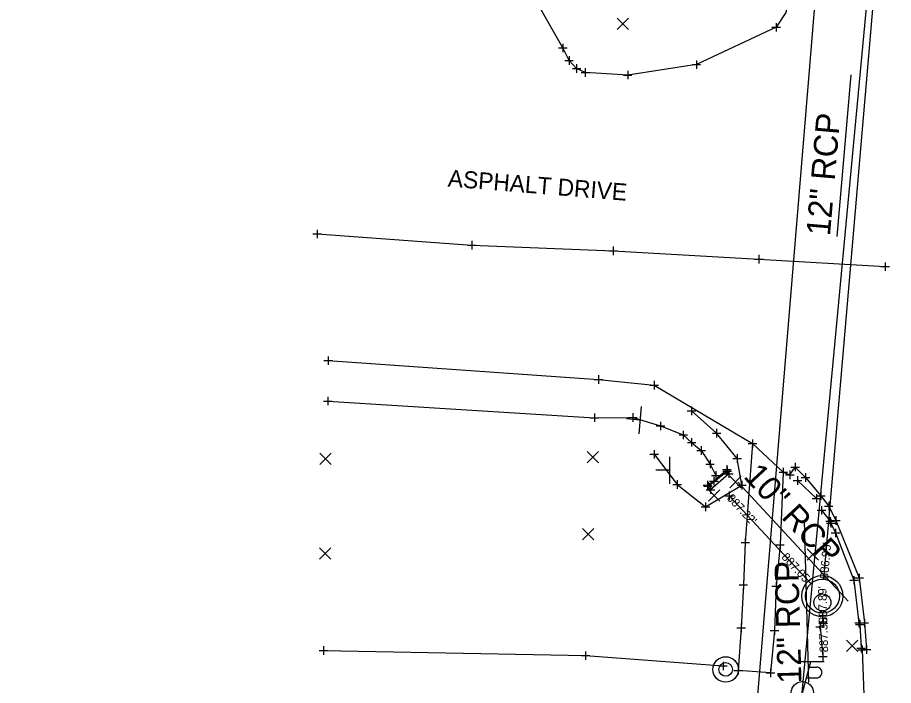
# Model space of a CAD drawing. Extents: x 1380440 to 1381945, y 468756 to 470369.
# Drawn here: x 1381467.5 to 1381570.5, y 469758.2 to 469836.8 of the extents above; entities that cross this region are included whole.
import ezdxf

# ---------------------------------------------------------------- set-up
doc = ezdxf.new("R2010")
doc.units = 0
for name, color, linetype in [('DR_P_Headwall', 7, 'Continuous'), ('DR_X_Cells', 7, 'Continuous'), ('DV_X_Lot_Line', 7, 'Continuous'), ('GE_P_Driveway_CL', 7, 'Continuous'), ('GK_Drainage_Nodes', 7, 'Continuous'), ('PV_P_Curb', 7, 'Continuous'), ('PV_P_Curb_Ramp', 7, 'Continuous'), ('PV_P_Drive', 7, 'Continuous'), ('PV_P_Joint', 7, 'Continuous'), ('PV_P_Parking_Lot', 7, 'Continuous'), ('PV_P_Saw_Cut_Line', 7, 'Continuous'), ('PV_X_COP', 7, 'Continuous'), ('RW_P_Esmt_TMP', 7, 'Continuous'), ('RW_X_CL', 7, 'Continuous'), ('SC_Scratch1', 7, 'Continuous'), ('SC_Scratch3', 7, 'Continuous'), ('SC_Shading1', 7, 'Continuous'), ('SH_Named_Boundary', 7, 'Continuous'), ('UT_X_Gas', 7, 'Continuous'), ('UT_X_Overhead_Combined', 7, 'Continuous'), ('X-CL', 7, 'Continuous'), ('X-SUBDIVISION', 7, 'Continuous')]:
    doc.layers.add(name, color=color, linetype=linetype)

msp = doc.modelspace()

# ---------------------------------------------------------------- linework, layer by layer
at = {"layer": 'DR_P_Headwall'}
for points in [[(1381553.91, 469786.69), (1381553.07, 469775.06), (1381552.84, 469770.08), (1381552.59, 469765.03), (1381552.22, 469760.02)], [(1381557.54, 469783.33), (1381557.15, 469774.79), (1381556.68, 469769.93), (1381556.5, 469764.72), (1381556.04, 469759.73), (1381552.22, 469760.02)]]:
    msp.add_lwpolyline(points, dxfattribs=at)
at = {"layer": 'DR_X_Cells'}
for points in [[(1381559.2, 469782.35), (1381561.45, 469780.25)], [(1381562.03, 469778.85), (1381563.05, 469777.56)], [(1381563.12, 469777.33), (1381563.68, 469776.18), (1381565.84, 469770.62), (1381566.43, 469765.62)], [(1381566.53, 469765.42), (1381566.69, 469762.64)]]:
    msp.add_lwpolyline(points, dxfattribs=at)
at = {"layer": 'DV_X_Lot_Line'}
msp.add_lwpolyline([(1381550.89, 469783.64), (1381549.38, 469782.29), (1381548.61, 469781.82)], dxfattribs=at)
at = {"layer": 'GE_P_Driveway_CL'}
for p, q in [((1381538.02, 469835.38), (1381539.35, 469836.71)), ((1381538.02, 469836.71), (1381539.35, 469835.38)), ((1381534.48, 469784.45), (1381535.82, 469785.78)), ((1381534.48, 469785.78), (1381535.82, 469784.45)), ((1381503.05, 469784.24), (1381504.38, 469785.58)), ((1381503.05, 469785.58), (1381504.38, 469784.24)), ((1381551.24, 469781.51), (1381552.57, 469782.85)), ((1381551.24, 469782.85), (1381552.57, 469781.51)), ((1381548.74, 469779.94), (1381550.07, 469781.27)), ((1381548.74, 469781.27), (1381550.07, 469779.94)), ((1381533.92, 469775.39), (1381535.26, 469776.72)), ((1381533.92, 469776.72), (1381535.26, 469775.39)), ((1381503, 469773.09), (1381504.33, 469774.42)), ((1381503, 469774.42), (1381504.33, 469773.09)), ((1381560.35, 469772.98), (1381561.69, 469774.31)), ((1381560.35, 469774.31), (1381561.69, 469772.98)), ((1381564.98, 469762.23), (1381566.31, 469763.57)), ((1381564.98, 469763.57), (1381566.31, 469762.23))]:
    msp.add_line(p, q, dxfattribs=at)
at = {"layer": 'GK_Drainage_Nodes'}
msp.add_lwpolyline([(1381503.48, 469762.36), (1381534.28, 469761.76), (1381550.45, 469760.54)], dxfattribs=at)
at = {"layer": 'PV_P_Curb'}
for points in [[(1381503.97, 469791.7), (1381535.33, 469789.74), (1381539.85, 469789.76), (1381543.1, 469788.77), (1381545.78, 469787.71), (1381546.76, 469786.84), (1381547.89, 469785.89), (1381548.92, 469784.29), (1381549.59, 469782.95)], [(1381561.88, 469765.13), (1381562.19, 469761.65)]]:
    msp.add_lwpolyline(points, dxfattribs=at)
at = {"layer": 'PV_P_Curb_Ramp'}
for p, q in [((1381562.13, 469770.76), (1381562.13, 469770.76)), ((1381562.13, 469768.76), (1381562.13, 469768.76)), ((1381562.13, 469768.76), (1381562.13, 469768.76)), ((1381562.13, 469768.01), (1381562.13, 469768.01)), ((1381562.13, 469766.76), (1381562.13, 469766.76))]:
    msp.add_line(p, q, dxfattribs=at)
msp.add_circle((1381562.13, 469768.76), 2, dxfattribs=at)
at = {"layer": 'PV_P_Drive'}
for p, q in [((1381540.84, 469791.05), (1381540.56, 469787.86)), ((1381540.7, 469789.46), (1381539.11, 469789.6)), ((1381544.16, 469785.15), (1381544.16, 469781.95)), ((1381544.16, 469783.55), (1381542.56, 469783.55))]:
    msp.add_line(p, q, dxfattribs=at)
at = {"layer": 'PV_P_Joint'}
for centre, radius in [((1381562.13, 469768.76), 2.42), ((1381562.13, 469768.76), 2), ((1381562.13, 469768.01), 1)]:
    msp.add_circle(centre, radius, dxfattribs=at)
at = {"layer": 'PV_P_Parking_Lot'}
msp.add_lwpolyline([(1381542.35, 469785.44), (1381545.05, 469781.89), (1381548.39, 469779.26), (1381552.66, 469781.8), (1381552.11, 469784.95), (1381549.7, 469787.92), (1381546.74, 469790.54)], dxfattribs=at)
at = {"layer": 'PV_P_Saw_Cut_Line'}
for p, q in [((1381551.19, 469781.06), (1381551.19, 469780.06)), ((1381550.69, 469780.56), (1381551.69, 469780.56)), ((1381551.19, 469780.56), (1381551.19, 469780.56)), ((1381561.72, 469765.59), (1381562.72, 469765.59)), ((1381562.22, 469766.09), (1381562.22, 469765.09)), ((1381562.22, 469765.59), (1381562.22, 469765.59))]:
    msp.add_line(p, q, dxfattribs=at)
at = {"layer": 'PV_X_COP'}
for p, q in [((1381560.74, 469761.01), (1381559.13, 469755.01)), ((1381562.34, 469761.01), (1381559.14, 469761.01)), ((1381560.58, 469760.41), (1381561.43, 469760.41)), ((1381560.24, 469759.13), (1381561.43, 469759.13))]:
    msp.add_line(p, q, dxfattribs=at)
msp.add_circle((1381559.77, 469757.41), 1.3, dxfattribs=at)
msp.add_arc((1381561.44, 469759.77), 0.638, 268.8767, 91.1233, dxfattribs=at)
at = {"layer": 'RW_P_Esmt_TMP'}
for points in [[(1381558.35, 469840.14), (1381557.85, 469837.4), (1381556.7, 469835.65), (1381547.32, 469831.26), (1381539.24, 469830.04), (1381534.26, 469830.33), (1381533.24, 469830.81), (1381532.35, 469831.75), (1381531.61, 469833.22), (1381528.74, 469838.25), (1381528.06, 469839.33), (1381527.53, 469840.55), (1381527.51, 469841.81), (1381527.73, 469842.93), (1381527.99, 469844.34), (1381528.64, 469852.75), (1381545.21, 469852.93)], [(1381504.03, 469796.45), (1381535.81, 469794.23), (1381542.35, 469793.56), (1381553.91, 469786.69), (1381557.54, 469783.33), (1381558.31, 469783.03), (1381558.93, 469783.94), (1381560.15, 469782.7), (1381561.95, 469780.57), (1381562.88, 469779.33), (1381563.72, 469777.65), (1381566.46, 469770.89), (1381567.07, 469765.6), (1381567.32, 469762.48), (1381566.8, 469762.44), (1381567.31, 469748.74), (1381566.9, 469746.97), (1381566.29, 469730.74), (1381565.48, 469712.75), (1381565.27, 469710.06), (1381564.07, 469691.21), (1381563.72, 469691.13), (1381563.05, 469684.22)]]:
    msp.add_lwpolyline(points, dxfattribs=at)
at = {"layer": 'RW_X_CL'}
for p, q in [((1381565.48, 469830.07), (1381563.85, 469811.05)), ((1381565.16, 469768.17), (1381552.19, 469782.16)), ((1381559.99, 469777.66), (1381560.5, 469758.58))]:
    msp.add_line(p, q, dxfattribs=at)
at = {"layer": 'SC_Scratch1'}
for radius in [1.5, 0.8]:
    msp.add_circle((1381550.76, 469760.13), radius, dxfattribs=at)
at = {"layer": 'SC_Scratch3'}
msp.add_lwpolyline([(1381548.97, 469781.27), (1381548.69, 469781.67), (1381550.93, 469783.46), (1381551.13, 469783.15)], close=True, dxfattribs=at)
at = {"layer": 'SC_Shading1'}
msp.add_lwpolyline([(1381502.74, 469811.35), (1381520.93, 469810.03), (1381537.52, 469809.37), (1381554.67, 469808.38), (1381569.52, 469807.51)], dxfattribs=at)
at = {"layer": 'SH_Named_Boundary'}
for p, q in [((1381556.2, 469835.65), (1381557.2, 469835.65)), ((1381556.7, 469836.15), (1381556.7, 469835.15)), ((1381556.7, 469835.65), (1381556.7, 469835.65)), ((1381531.11, 469833.22), (1381532.11, 469833.22)), ((1381531.61, 469833.72), (1381531.61, 469832.72)), ((1381531.61, 469833.22), (1381531.61, 469833.22)), ((1381532.35, 469832.25), (1381532.35, 469831.25)), ((1381531.85, 469831.75), (1381532.85, 469831.75)), ((1381532.35, 469831.75), (1381532.35, 469831.75)), ((1381533.24, 469831.31), (1381533.24, 469830.31)), ((1381546.82, 469831.26), (1381547.82, 469831.26)), ((1381546.82, 469831.26), (1381547.82, 469831.26)), ((1381547.32, 469831.76), (1381547.32, 469830.76)), ((1381547.32, 469831.76), (1381547.32, 469830.76)), ((1381547.32, 469831.26), (1381547.32, 469831.26)), ((1381547.32, 469831.26), (1381547.32, 469831.26)), ((1381532.74, 469830.81), (1381533.74, 469830.81)), ((1381533.24, 469830.81), (1381533.24, 469830.81)), ((1381533.76, 469830.33), (1381534.76, 469830.33)), ((1381533.76, 469830.33), (1381534.76, 469830.33)), ((1381534.26, 469830.83), (1381534.26, 469829.83)), ((1381534.26, 469830.83), (1381534.26, 469829.83)), ((1381534.26, 469830.33), (1381534.26, 469830.33)), ((1381534.26, 469830.33), (1381534.26, 469830.33)), ((1381539.24, 469830.54), (1381539.24, 469829.54)), ((1381538.74, 469830.04), (1381539.74, 469830.04)), ((1381539.24, 469830.04), (1381539.24, 469830.04)), ((1381502.74, 469811.85), (1381502.74, 469810.85)), ((1381502.24, 469811.35), (1381503.24, 469811.35)), ((1381502.74, 469811.35), (1381502.74, 469811.35)), ((1381520.93, 469810.53), (1381520.93, 469809.53)), ((1381520.43, 469810.03), (1381521.43, 469810.03)), ((1381520.93, 469810.03), (1381520.93, 469810.03)), ((1381537.52, 469809.87), (1381537.52, 469808.87)), ((1381537.02, 469809.37), (1381538.02, 469809.37)), ((1381537.52, 469809.37), (1381537.52, 469809.37)), ((1381554.67, 469808.88), (1381554.67, 469807.88)), ((1381554.17, 469808.38), (1381555.17, 469808.38)), ((1381554.67, 469808.38), (1381554.67, 469808.38)), ((1381569.02, 469807.51), (1381570.02, 469807.51)), ((1381569.52, 469808.01), (1381569.52, 469807.01)), ((1381569.52, 469807.51), (1381569.52, 469807.51)), ((1381503.53, 469796.45), (1381504.53, 469796.45)), ((1381504.03, 469796.95), (1381504.03, 469795.95)), ((1381504.03, 469796.45), (1381504.03, 469796.45)), ((1381535.31, 469794.23), (1381536.31, 469794.23)), ((1381535.81, 469794.73), (1381535.81, 469793.73)), ((1381535.81, 469794.23), (1381535.81, 469794.23)), ((1381542.35, 469794.06), (1381542.35, 469793.06)), ((1381541.85, 469793.56), (1381542.85, 469793.56)), ((1381542.35, 469793.56), (1381542.35, 469793.56)), ((1381503.97, 469792.2), (1381503.97, 469791.2)), ((1381503.47, 469791.7), (1381504.47, 469791.7)), ((1381503.97, 469791.7), (1381503.97, 469791.7)), ((1381546.74, 469791.04), (1381546.74, 469790.04)), ((1381535.33, 469790.24), (1381535.33, 469789.24)), ((1381539.85, 469790.26), (1381539.85, 469789.26)), ((1381546.24, 469790.54), (1381547.24, 469790.54)), ((1381546.74, 469790.54), (1381546.74, 469790.54)), ((1381534.83, 469789.74), (1381535.83, 469789.74)), ((1381535.33, 469789.74), (1381535.33, 469789.74)), ((1381539.35, 469789.76), (1381540.35, 469789.76)), ((1381539.85, 469789.76), (1381539.85, 469789.76)), ((1381543.1, 469789.27), (1381543.1, 469788.27)), ((1381542.6, 469788.77), (1381543.6, 469788.77)), ((1381543.1, 469788.77), (1381543.1, 469788.77)), ((1381545.78, 469788.21), (1381545.78, 469787.21)), ((1381549.2, 469787.92), (1381550.2, 469787.92)), ((1381549.7, 469788.42), (1381549.7, 469787.42)), ((1381549.7, 469787.92), (1381549.7, 469787.92)), ((1381545.28, 469787.71), (1381546.28, 469787.71)), ((1381545.78, 469787.71), (1381545.78, 469787.71)), ((1381546.26, 469786.84), (1381547.26, 469786.84)), ((1381546.76, 469787.34), (1381546.76, 469786.34)), ((1381546.76, 469786.84), (1381546.76, 469786.84)), ((1381553.91, 469787.19), (1381553.91, 469786.19)), ((1381553.91, 469787.19), (1381553.91, 469786.19)), ((1381542.35, 469785.94), (1381542.35, 469784.94)), ((1381547.39, 469785.89), (1381548.39, 469785.89)), ((1381547.89, 469786.39), (1381547.89, 469785.39)), ((1381547.89, 469785.89), (1381547.89, 469785.89)), ((1381553.41, 469786.69), (1381554.41, 469786.69)), ((1381553.41, 469786.69), (1381554.41, 469786.69)), ((1381553.91, 469786.69), (1381553.91, 469786.69)), ((1381553.91, 469786.69), (1381553.91, 469786.69)), ((1381541.85, 469785.44), (1381542.85, 469785.44)), ((1381542.35, 469785.44), (1381542.35, 469785.44)), ((1381548.92, 469784.79), (1381548.92, 469783.79)), ((1381551.61, 469784.95), (1381552.61, 469784.95)), ((1381552.11, 469785.45), (1381552.11, 469784.45)), ((1381552.11, 469784.95), (1381552.11, 469784.95)), ((1381548.42, 469784.29), (1381549.42, 469784.29)), ((1381548.92, 469784.29), (1381548.92, 469784.29)), ((1381550.89, 469784.14), (1381550.89, 469783.14)), ((1381550.93, 469783.96), (1381550.93, 469782.96)), ((1381557.54, 469783.83), (1381557.54, 469782.83)), ((1381557.54, 469783.83), (1381557.54, 469782.83)), ((1381558.43, 469783.94), (1381559.43, 469783.94)), ((1381558.93, 469784.44), (1381558.93, 469783.44)), ((1381558.93, 469783.94), (1381558.93, 469783.94)), ((1381549.09, 469782.95), (1381550.09, 469782.95)), ((1381549.38, 469782.79), (1381549.38, 469781.79)), ((1381549.59, 469783.45), (1381549.59, 469782.45)), ((1381549.59, 469782.95), (1381549.59, 469782.95)), ((1381550.39, 469783.64), (1381551.39, 469783.64)), ((1381550.43, 469783.46), (1381551.43, 469783.46)), ((1381550.63, 469783.15), (1381551.63, 469783.15)), ((1381550.89, 469783.64), (1381550.89, 469783.64)), ((1381550.93, 469783.46), (1381550.93, 469783.46)), ((1381551.13, 469783.65), (1381551.13, 469782.65)), ((1381551.13, 469783.15), (1381551.13, 469783.15)), ((1381557.04, 469783.33), (1381558.04, 469783.33)), ((1381557.04, 469783.33), (1381558.04, 469783.33)), ((1381557.54, 469783.33), (1381557.54, 469783.33)), ((1381557.54, 469783.33), (1381557.54, 469783.33)), ((1381557.81, 469783.03), (1381558.81, 469783.03)), ((1381558.31, 469783.53), (1381558.31, 469782.53)), ((1381558.31, 469783.03), (1381558.31, 469783.03)), ((1381559.2, 469782.85), (1381559.2, 469781.85)), ((1381559.65, 469782.7), (1381560.65, 469782.7)), ((1381560.15, 469783.2), (1381560.15, 469782.2)), ((1381560.15, 469782.7), (1381560.15, 469782.7)), ((1381544.55, 469781.89), (1381545.55, 469781.89)), ((1381545.05, 469782.39), (1381545.05, 469781.39)), ((1381545.05, 469781.89), (1381545.05, 469781.89)), ((1381548.11, 469781.82), (1381549.11, 469781.82)), ((1381548.19, 469781.67), (1381549.19, 469781.67)), ((1381548.61, 469782.32), (1381548.61, 469781.32)), ((1381548.61, 469781.82), (1381548.61, 469781.82)), ((1381548.69, 469782.17), (1381548.69, 469781.17)), ((1381548.69, 469781.67), (1381548.69, 469781.67)), ((1381548.88, 469782.29), (1381549.88, 469782.29)), ((1381548.97, 469781.77), (1381548.97, 469780.77)), ((1381549.38, 469782.29), (1381549.38, 469782.29)), ((1381552.16, 469781.8), (1381553.16, 469781.8)), ((1381552.66, 469782.3), (1381552.66, 469781.3)), ((1381552.66, 469781.8), (1381552.66, 469781.8)), ((1381558.7, 469782.35), (1381559.7, 469782.35)), ((1381559.2, 469782.35), (1381559.2, 469782.35)), ((1381548.47, 469781.27), (1381549.47, 469781.27)), ((1381548.97, 469781.27), (1381548.97, 469781.27)), ((1381561.45, 469780.75), (1381561.45, 469779.75)), ((1381561.95, 469781.07), (1381561.95, 469780.07)), ((1381548.39, 469779.76), (1381548.39, 469778.76)), ((1381560.95, 469780.25), (1381561.95, 469780.25)), ((1381561.45, 469780.57), (1381562.45, 469780.57)), ((1381561.45, 469780.25), (1381561.45, 469780.25)), ((1381561.95, 469780.57), (1381561.95, 469780.57)), ((1381562.88, 469779.83), (1381562.88, 469778.83)), ((1381547.89, 469779.26), (1381548.89, 469779.26)), ((1381548.39, 469779.26), (1381548.39, 469779.26)), ((1381561.53, 469778.85), (1381562.53, 469778.85)), ((1381562.03, 469779.35), (1381562.03, 469778.35)), ((1381562.03, 469778.85), (1381562.03, 469778.85)), ((1381562.38, 469779.33), (1381563.38, 469779.33)), ((1381562.88, 469779.33), (1381562.88, 469779.33)), ((1381562.55, 469777.56), (1381563.55, 469777.56)), ((1381563.05, 469778.06), (1381563.05, 469777.06)), ((1381563.05, 469777.56), (1381563.05, 469777.56)), ((1381563.12, 469777.83), (1381563.12, 469776.83)), ((1381563.22, 469777.65), (1381564.22, 469777.65)), ((1381563.22, 469777.65), (1381564.22, 469777.65)), ((1381563.72, 469778.15), (1381563.72, 469777.15)), ((1381563.72, 469778.15), (1381563.72, 469777.15)), ((1381563.72, 469777.65), (1381563.72, 469777.65)), ((1381563.72, 469777.65), (1381563.72, 469777.65)), ((1381562.62, 469777.33), (1381563.62, 469777.33)), ((1381563.12, 469777.33), (1381563.12, 469777.33)), ((1381563.68, 469776.68), (1381563.68, 469775.68)), ((1381563.68, 469776.68), (1381563.68, 469775.68)), ((1381553.07, 469775.56), (1381553.07, 469774.56)), ((1381563.18, 469776.18), (1381564.18, 469776.18)), ((1381563.18, 469776.18), (1381564.18, 469776.18)), ((1381563.68, 469776.18), (1381563.68, 469776.18)), ((1381563.68, 469776.18), (1381563.68, 469776.18)), ((1381552.57, 469775.06), (1381553.57, 469775.06)), ((1381553.07, 469775.06), (1381553.07, 469775.06)), ((1381556.65, 469774.79), (1381557.65, 469774.79)), ((1381557.15, 469775.29), (1381557.15, 469774.29)), ((1381557.15, 469774.79), (1381557.15, 469774.79)), ((1381566.46, 469771.39), (1381566.46, 469770.39)), ((1381552.84, 469770.58), (1381552.84, 469769.58)), ((1381556.68, 469770.43), (1381556.68, 469769.43)), ((1381565.34, 469770.62), (1381566.34, 469770.62)), ((1381565.84, 469771.12), (1381565.84, 469770.12)), ((1381565.84, 469770.62), (1381565.84, 469770.62)), ((1381565.96, 469770.89), (1381566.96, 469770.89)), ((1381566.46, 469770.89), (1381566.46, 469770.89)), ((1381552.34, 469770.08), (1381553.34, 469770.08)), ((1381552.84, 469770.08), (1381552.84, 469770.08)), ((1381556.18, 469769.93), (1381557.18, 469769.93)), ((1381556.68, 469769.93), (1381556.68, 469769.93)), ((1381552.59, 469765.53), (1381552.59, 469764.53)), ((1381556.5, 469765.22), (1381556.5, 469764.22)), ((1381561.88, 469765.63), (1381561.88, 469764.63)), ((1381565.93, 469765.62), (1381566.93, 469765.62)), ((1381565.93, 469765.62), (1381566.93, 469765.62)), ((1381566.03, 469765.42), (1381567.03, 469765.42)), ((1381566.43, 469766.12), (1381566.43, 469765.12)), ((1381566.43, 469766.12), (1381566.43, 469765.12)), ((1381566.43, 469765.62), (1381566.43, 469765.62)), ((1381566.43, 469765.62), (1381566.43, 469765.62)), ((1381566.53, 469765.92), (1381566.53, 469764.92)), ((1381566.53, 469765.42), (1381566.53, 469765.42)), ((1381566.57, 469765.6), (1381567.57, 469765.6)), ((1381566.57, 469765.6), (1381567.57, 469765.6)), ((1381567.07, 469766.1), (1381567.07, 469765.1)), ((1381567.07, 469766.1), (1381567.07, 469765.1)), ((1381567.07, 469765.6), (1381567.07, 469765.6)), ((1381567.07, 469765.6), (1381567.07, 469765.6)), ((1381552.09, 469765.03), (1381553.09, 469765.03)), ((1381552.59, 469765.03), (1381552.59, 469765.03)), ((1381556, 469764.72), (1381557, 469764.72)), ((1381556.5, 469764.72), (1381556.5, 469764.72)), ((1381561.38, 469765.13), (1381562.38, 469765.13)), ((1381561.88, 469765.13), (1381561.88, 469765.13)), ((1381566.69, 469763.14), (1381566.69, 469762.14)), ((1381502.98, 469762.36), (1381503.98, 469762.36)), ((1381503.48, 469762.86), (1381503.48, 469761.86)), ((1381503.48, 469762.36), (1381503.48, 469762.36)), ((1381534.28, 469762.26), (1381534.28, 469761.26)), ((1381562.19, 469762.15), (1381562.19, 469761.15)), ((1381566.19, 469762.64), (1381567.19, 469762.64)), ((1381566.3, 469762.44), (1381567.3, 469762.44)), ((1381566.69, 469762.64), (1381566.69, 469762.64)), ((1381566.8, 469762.94), (1381566.8, 469761.94)), ((1381566.8, 469762.44), (1381566.8, 469762.44)), ((1381566.82, 469762.48), (1381567.82, 469762.48)), ((1381567.32, 469762.98), (1381567.32, 469761.98)), ((1381567.32, 469762.48), (1381567.32, 469762.48)), ((1381533.78, 469761.76), (1381534.78, 469761.76)), ((1381534.28, 469761.76), (1381534.28, 469761.76)), ((1381561.69, 469761.65), (1381562.69, 469761.65)), ((1381562.19, 469761.65), (1381562.19, 469761.65)), ((1381549.95, 469760.54), (1381550.95, 469760.54)), ((1381550.45, 469761.04), (1381550.45, 469760.04)), ((1381550.45, 469760.54), (1381550.45, 469760.54)), ((1381552.22, 469760.52), (1381552.22, 469759.52)), ((1381552.22, 469760.52), (1381552.22, 469759.52)), ((1381556.04, 469760.23), (1381556.04, 469759.23)), ((1381551.72, 469760.02), (1381552.72, 469760.02)), ((1381551.72, 469760.02), (1381552.72, 469760.02)), ((1381552.22, 469760.02), (1381552.22, 469760.02)), ((1381552.22, 469760.02), (1381552.22, 469760.02)), ((1381555.54, 469759.73), (1381556.54, 469759.73)), ((1381556.04, 469759.73), (1381556.04, 469759.73))]:
    msp.add_line(p, q, dxfattribs=at)
at = {"layer": 'UT_X_Gas'}
msp.add_lwpolyline([(1381485.9, 468926.41), (1381594.27, 470237.89), (1380558, 470279.29)], dxfattribs=at)
at = {"layer": 'UT_X_Overhead_Combined'}
msp.add_lwpolyline([(1381540.8, 469054.26), (1381515.28, 469203.1), (1381529.17, 469390.12), (1381543.86, 469565.78), (1381559.77, 469757.41), (1381571.97, 469887.64), (1381581.26, 470018.2), (1381595.79, 470220.83), (1381665.56, 470247.4)], dxfattribs=at)
at = {"layer": 'X-CL'}
for p, q in [((1381562.3, 469770.76), (1381570.47, 469866.05)), ((1381551.19, 469780.56), (1381560.77, 469770.23)), ((1381562.22, 469765.59), (1381562.19, 469766.76))]:
    msp.add_line(p, q, dxfattribs=at)

# ---------------------------------------------------------------- texts
at = {"layer": 'RW_X_CL'}
for s, rotation, p in [('12" RCP', 85.1034, (1381563.02, 469811.06)), ('10" RCP', 312.8329, (1381552.75, 469782.77)), ('12" RCP', 91.533, (1381559.68, 469758.5))]:
    msp.add_text(s, height=2.8, rotation=rotation, dxfattribs=at).set_placement(p)
at = {"layer": 'SC_Scratch1'}
for s, rotation, p in [("887.22'", 312.8329, (1381550.83, 469780.22)), ("886.95'", 85.1034, (1381562.8, 469770.71)), ("887.05'", 312.8329, (1381557.26, 469773.29)), ("887.89'", 91.533, (1381562.72, 469765.6)), ("887.35'", 91.533, (1381562.81, 469762.15))]:
    msp.add_text(s, height=1, rotation=rotation, dxfattribs=at).set_placement(p)
at = {"layer": 'X-SUBDIVISION'}
msp.add_text('ASPHALT DRIVE', height=2, rotation=355.4428, dxfattribs=at).set_placement((1381518.05, 469816.93))

doc.saveas('drawing.dxf')
